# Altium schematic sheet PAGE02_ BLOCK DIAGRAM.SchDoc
size 246 x 182 mm
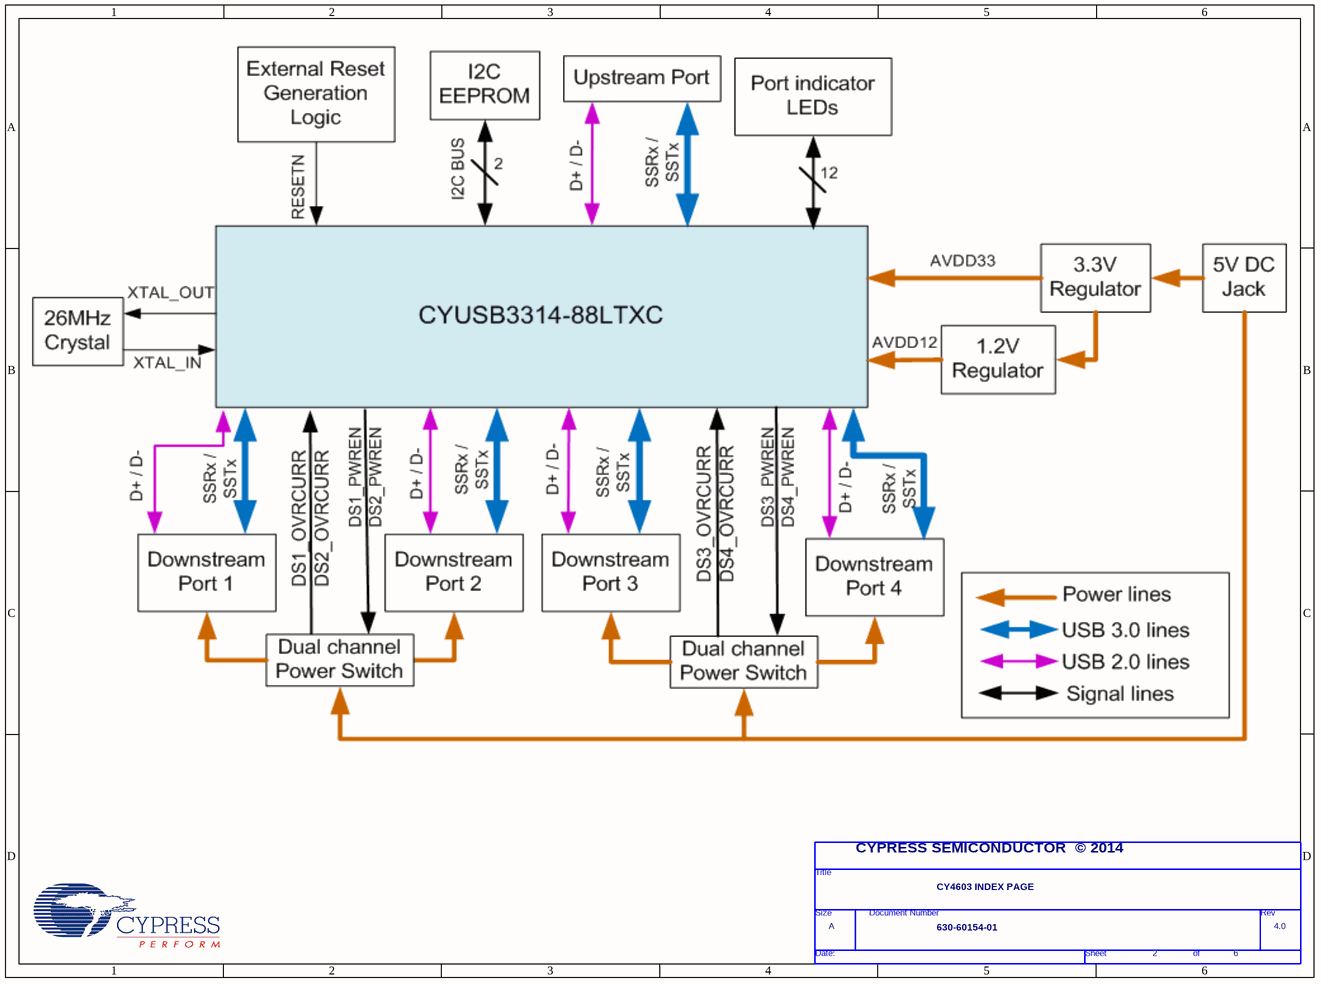
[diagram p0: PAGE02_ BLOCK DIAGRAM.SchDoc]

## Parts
*  Page Count: 6  Page Number: 2  Page Size: A  Title: CY4603 INDEX PAGE  RevCode: 4.0  Doc: 630-60154-01  (hidden comment: TitleBlock0)  (graphical)

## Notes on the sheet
- (near *) CYPRESS SEMICONDUCTOR  © 2014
